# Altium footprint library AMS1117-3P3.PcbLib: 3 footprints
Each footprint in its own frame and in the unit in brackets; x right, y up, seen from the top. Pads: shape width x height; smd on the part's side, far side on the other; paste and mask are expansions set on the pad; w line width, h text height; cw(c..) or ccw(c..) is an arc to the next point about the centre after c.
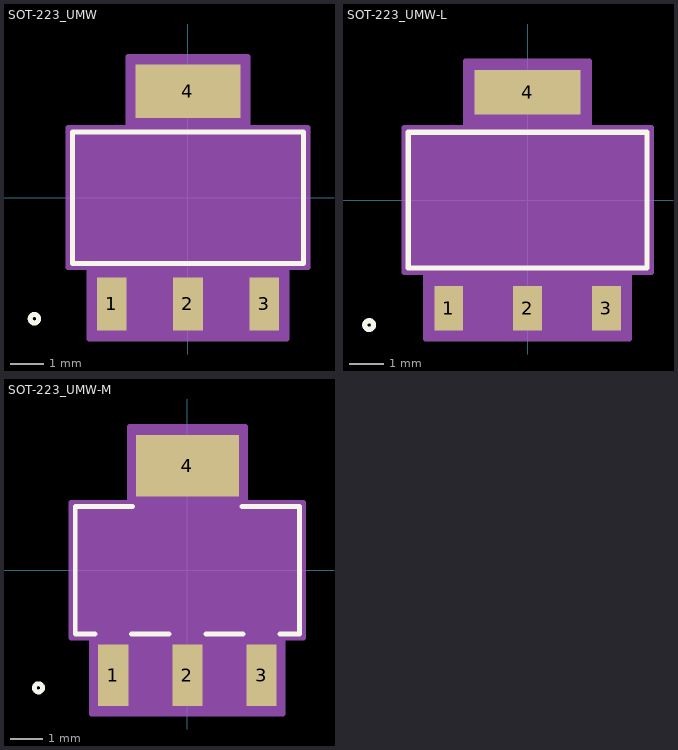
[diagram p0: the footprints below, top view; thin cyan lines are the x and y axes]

## SOT-223_UMW [mil]
pads (4):
  rect 35x63 smd paste+0 mask+0: 1(-90.55,-126) 2(0,-126) 3(90.55,-126)
  rect 124x63 smd paste+0 mask+0: 4(0,126)
Top Overlay:
  circle w6: c-182,-143.5 r5
  lines w6: -137,-78 137,-78 137,78 -137,78 -137,-78
  text ".Designator" at -137.5,-25 h50
Mechanical 13:
  circle w1: c-122,-63 r5
  lines w1: -132,-73 132,-73 132,73 -132,73 -132,-73 ; -107.05,-143.5 -107.05,-73 -74.05,-73 -74.05,-143.5 -107.05,-143.5 ; -61,73 61,73 61,143.5 -61,143.5 -61,73 ; -16.5,-143.5 -16.5,-73 16.5,-73 16.5,-143.5 -16.5,-143.5 ; 74.05,-143.5 74.05,-73 107.05,-73 107.05,-143.5 74.05,-143.5
  text ".Designator" at -137.5,-25 h50
Mechanical 15:
  region: -142,-83 -142,83 -71,83 -71,167.5 71,167.5 71,83 142,83 142,-83 117.05,-83 117.05,-167.5 -117.05,-167.5 -117.05,-83
  lines w6: -142,-83 -142,83 -71,83 -71,167.5 71,167.5 71,83 142,83 142,-83 117.05,-83 117.05,-167.5 -117.05,-167.5 -117.05,-83 -142,-83
3D body "SOT-223_UMW.step": height 71.1, standoff 0, extent -132.01,-143.5 132.01,143.5

## SOT-223_UMW-L [mil]
pads (4):
  rect 33x51 smd paste+0 mask+0: 1(-90.55,-124) 2(0,-124) 3(90.55,-124)
  rect 122x51 smd paste+0 mask+0: 4(0,124)
Top Overlay:
  circle w6: c-182,-143.5 r5
  lines w6: -137,-78 137,-78 137,78 -137,78 -137,-78
  text ".Designator" at -137.5,-25 h50
Mechanical 13:
  circle w1: c-122,-63 r5
  lines w1: -132,-73 132,-73 132,73 -132,73 -132,-73 ; -107.05,-143.5 -107.05,-73 -74.05,-73 -74.05,-143.5 -107.05,-143.5 ; -61,73 61,73 61,143.5 -61,143.5 -61,73 ; -16.5,-143.5 -16.5,-73 16.5,-73 16.5,-143.5 -16.5,-143.5 ; 74.05,-143.5 74.05,-73 107.05,-73 107.05,-143.5 74.05,-143.5
  text ".Designator" at -137.5,-25 h50
Mechanical 15:
  region: -142,-83 -142,83 -71,83 -71,159.5 71,159.5 71,83 142,83 142,-83 117.05,-83 117.05,-159.5 -117.05,-159.5 -117.05,-83
  lines w6: -142,-83 -142,83 -71,83 -71,159.5 71,159.5 71,83 142,83 142,-83 117.05,-83 117.05,-159.5 -117.05,-159.5 -117.05,-83 -142,-83
3D body "SOT-223_UMW.step": height 71.1, standoff 0, extent -132.01,-143.5 132.01,143.5

## SOT-223_UMW-M [mil]
pads (4):
  rect 37x75 smd paste+0 mask+0: 1(-90.55,-128) 2(0,-128) 3(90.55,-128)
  rect 126x75 smd paste+0 mask+0: 4(0,128)
Top Overlay:
  circle w6: c-182,-143.5 r5
  lines w6: -112.97,-78 -137,-78 -137,78 -66.92,78 ; -68.13,-78 -22.42,-78 ; 22.42,-78 68.13,-78 ; 66.92,78 137,78 137,-78 112.97,-78
  text ".Designator" at -137.5,-25 h50
Mechanical 13:
  circle w1: c-122,-63 r5
  lines w1: -132,-73 132,-73 132,73 -132,73 -132,-73 ; -107.05,-143.5 -107.05,-73 -74.05,-73 -74.05,-143.5 -107.05,-143.5 ; -61,73 61,73 61,143.5 -61,143.5 -61,73 ; -16.5,-143.5 -16.5,-73 16.5,-73 16.5,-143.5 -16.5,-143.5 ; 74.05,-143.5 74.05,-73 107.05,-73 107.05,-143.5 74.05,-143.5
  text ".Designator" at -137.5,-25 h50
Mechanical 15:
  region: -142,-83 -142,83 -71,83 -71,175.5 71,175.5 71,83 142,83 142,-83 117.05,-83 117.05,-175.5 -117.05,-175.5 -117.05,-83
  lines w6: -142,-83 -142,83 -71,83 -71,175.5 71,175.5 71,83 142,83 142,-83 117.05,-83 117.05,-175.5 -117.05,-175.5 -117.05,-83 -142,-83
3D body "SOT-223_UMW.step": height 71.1, standoff 0, extent -132.01,-143.5 132.01,143.5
